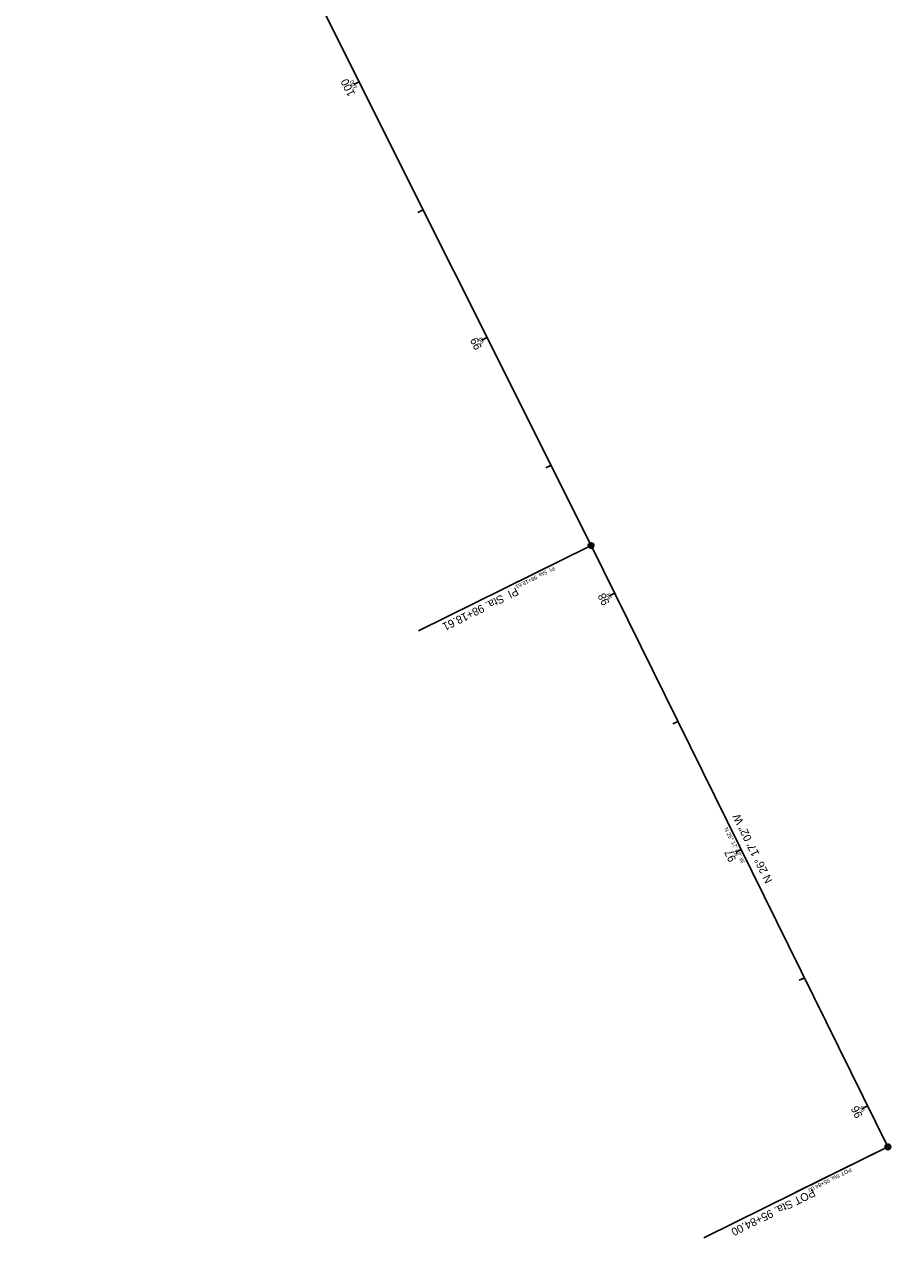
# Model space of a CAD drawing. Extents: x 1715640 to 1716553, y 394047 to 395910.
# Drawn here: x 1716249.5 to 1716552.7, y 394046.9 to 394471.5 of the extents above; entities that cross this region are included whole.
import ezdxf

# ---------------------------------------------------------------- set-up
doc = ezdxf.new("R2010")
doc.units = 0
doc.layers.add('GE_P_CL_10', color=7, linetype='Continuous')
doc.layers.add('GE_P_CL_20', color=7, linetype='Continuous')

msp = doc.modelspace()

# ---------------------------------------------------------------- linework, layer by layer
at = {"layer": 'GE_P_CL_10'}
for p, q in [((1716447.81, 394289.08), (1716249.46, 394685.42)), ((1716366.63, 394451.29), (1716365.74, 394450.85)), ((1716389.01, 394406.58), (1716388.11, 394406.13)), ((1716411.38, 394361.87), (1716410.49, 394361.42)), ((1716433.76, 394317.15), (1716432.87, 394316.71)), ((1716447.36, 394288.86), (1716417.65, 394274.19)), ((1716551.7, 394078.73), (1716447.81, 394289.08)), ((1716456.05, 394272.4), (1716455.15, 394271.95)), ((1716478.19, 394227.57), (1716477.29, 394227.12)), ((1716500.33, 394182.73), (1716499.43, 394182.29)), ((1716522.47, 394137.9), (1716521.58, 394137.46)), ((1716544.61, 394093.07), (1716543.72, 394092.63)), ((1716551.25, 394078.51), (1716519.52, 394062.83))]:
    msp.add_line(p, q, dxfattribs=at)
for centre in [(1716447.81, 394289.08), (1716551.7, 394078.73)]:
    msp.add_circle(centre, 0.5, dxfattribs=at)
at = {"layer": 'GE_P_CL_20'}
for p, q in [((1716447.81, 394289.08), (1716249.46, 394685.42)), ((1716366.63, 394451.29), (1716364.84, 394450.4)), ((1716389.01, 394406.58), (1716387.22, 394405.68)), ((1716411.38, 394361.87), (1716409.6, 394360.97)), ((1716433.76, 394317.15), (1716431.97, 394316.26)), ((1716446.91, 394288.64), (1716387.48, 394259.29)), ((1716551.7, 394078.73), (1716447.81, 394289.08)), ((1716456.05, 394272.4), (1716454.26, 394271.51)), ((1716478.19, 394227.57), (1716476.4, 394226.68)), ((1716500.33, 394182.73), (1716498.54, 394181.85)), ((1716522.47, 394137.9), (1716520.68, 394137.02)), ((1716544.61, 394093.07), (1716542.82, 394092.19)), ((1716550.8, 394078.28), (1716487.34, 394046.94))]:
    msp.add_line(p, q, dxfattribs=at)
for centre in [(1716447.81, 394289.08), (1716551.7, 394078.73)]:
    msp.add_circle(centre, 1, dxfattribs=at)

# ---------------------------------------------------------------- texts
at = {"layer": 'GE_P_CL_10'}
for s, rotation, p in [('100', 116.5857, (1716365.99, 394449.23)), ('99', 116.5857, (1716410.56, 394360.17)), ('PI  Sta. 98+18.61', 206.2838, (1716434.67, 394281.81)), ('98', 116.2838, (1716455.2, 394270.72)), ('N 26%%d 17\' 02" W', 296.2838, (1716494.37, 394190.07)), ('97', 116.2838, (1716499.51, 394181.01)), ('96', 116.2838, (1716543.78, 394091.37)), ('POT Sta. 95+84.00', 206.2838, (1716538.56, 394071.46))]:
    msp.add_text(s, height=1.4, rotation=rotation, dxfattribs=at).set_placement(p)
at = {"layer": 'GE_P_CL_20'}
for s, rotation, p in [('100', 116.5857, (1716365.34, 394447.16)), ('99', 116.5857, (1716409.73, 394358.47)), ('PI  Sta. 98+18.61', 206.2838, (1716421.53, 394274.54)), ('98', 116.2838, (1716454.36, 394269.05)), ('N 26%%d 17\' 02" W', 116.2838, (1716511.44, 394171.83)), ('97', 116.2838, (1716498.69, 394179.28)), ('96', 116.2838, (1716542.95, 394089.67)), ('POT Sta. 95+84.00', 206.2838, (1716525.42, 394064.19))]:
    msp.add_text(s, height=2.8, rotation=rotation, dxfattribs=at).set_placement(p)

doc.saveas('drawing.dxf')
